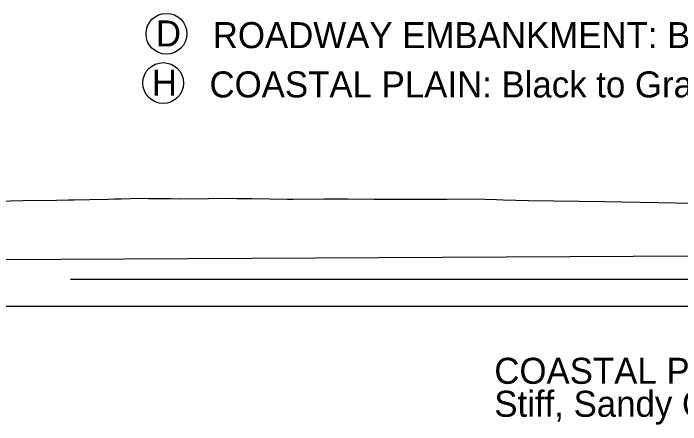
# Model space of a CAD drawing. Extents: x -516 to 303, y -10 to 5017.
# Drawn here: x 97.61 to 136.07, y 2493.17 to 2516.88 of the extents above; entities that cross this region are included whole.
import ezdxf

# ---------------------------------------------------------------- set-up
doc = ezdxf.new("R2010")
doc.units = 0
for name, color, linetype in [('Exist Cross Section Cell', 7, 'Continuous'), ('Exist XS Ground Line', 7, 'Continuous'), ('Prop Road Sect_ Material - Bubble + Leader + Bubble Tx', 7, 'Continuous'), ('Prop Road Sect_ Material - Contact (General - Major)', 7, 'Continuous'), ('Prop Road Sect_ Material - Contact (General - Minor)', 7, 'Continuous'), ('Prop Road Sect_ Material - Tx (Composite Desc)', 7, 'Continuous')]:
    doc.layers.add(name, color=color, linetype=linetype)

msp = doc.modelspace()

# ---------------------------------------------------------------- linework, layer by layer
at = {"layer": 'Exist Cross Section Cell'}
msp.add_line((0, 2500), (150, 2500), dxfattribs=at)
at = {"layer": 'Exist XS Ground Line'}
msp.add_lwpolyline([(95.976, 2506.034), (98.153, 2506.088), (100.105, 2506.118), (100.789, 2506.128), (101.114, 2506.135), (102.027, 2506.156), (103.067, 2506.18), (103.439, 2506.189), (103.82, 2506.196), (104.844, 2506.22), (105.394, 2506.213), (106.073, 2506.207), (106.678, 2506.202), (107.226, 2506.194), (108.865, 2506.203), (110.064, 2506.222), (110.494, 2506.217), (111.373, 2506.205), (113.407, 2506.176), (113.719, 2506.171), (115.532, 2506.198), (115.945, 2506.194), (116.457, 2506.187), (116.882, 2506.183), (118.413, 2506.174), (119.336, 2506.168), (120.659, 2506.169), (122.012, 2506.169), (122.616, 2506.172), (124.248, 2506.181), (124.807, 2506.18), (125.462, 2506.159), (125.837, 2506.141), (127.298, 2506.098), (131.676, 2506.039), (149.095, 2505.718)], dxfattribs=at)
at = {"layer": 'Prop Road Sect_ Material - Bubble + Leader + Bubble Tx'}
for centre in [(106.433, 2515.706), (106.244, 2512.866)]:
    msp.add_circle(centre, 1.176, dxfattribs=at)
at = {"layer": 'Prop Road Sect_ Material - Contact (General - Major)'}
msp.add_line((183.288, 2503.131), (7.012, 2502.209), dxfattribs=at)
at = {"layer": 'Prop Road Sect_ Material - Contact (General - Minor)'}
msp.add_line((100.895, 2501.557), (189.898, 2501.557), dxfattribs=at)

# ---------------------------------------------------------------- texts
at = {"layer": 'Prop Road Sect_ Material - Tx (Composite Desc)'}
for s, p in [('D', (105.828, 2514.974)), ('ROADWAY EMBANKMENT: Brown, Medium Stiff to Stiff, Silty CLAY (A-7-6), Highly Plastic, Moist', (109.105, 2514.876)), ('H', (105.592, 2512.134)), ('COASTAL PLAIN: Black to Gray, Stiff, Sandy SILT (A-4), Moist (Black Creek Formation)', (108.916, 2512.035)), ('COASTAL PLAIN: Orange-Brown and Gray, Soft to Medium ', (125.332, 2495.527)), ('Stiff, Sandy CLAY (A-6), Moist to Wet (Black Creek Formation)', (125.332, 2493.626))]:
    msp.add_text(s, height=1.5, dxfattribs=at).set_placement(p)

doc.saveas('drawing.dxf')
